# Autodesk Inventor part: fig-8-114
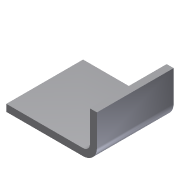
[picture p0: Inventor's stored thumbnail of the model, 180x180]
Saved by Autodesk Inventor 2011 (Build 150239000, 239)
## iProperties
Created: 2009-09
Part Number: fig-8-114
Document SubType Name: Modeling
Designer: Sham
Density: 1 g/cm^3
Author: Sham
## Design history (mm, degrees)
sketch "Sketch1"
  geometry: L1 (-33.976, 22)-(0, 22); L2 (0, 22)-(0, 0); L3 (0, 0)-(-33.976, 0); L4 (-33.976, 0)-(-33.976, 22)
  constraints: 8 end point, 2 parallel, 1 horizontal, 1 perpendicular
extrude "Extrusion1" new body sketch "Sketch1" distance "d0" = 2; taper "d1" = 0 deg
sketch "Sketch2"
  geometry: L1 (-12, 22)-(-12, 0)
  constraints: 2 end point
feature "Bend Part1" sketch "Sketch2" dims "d5" = 90 deg, "d6" = 2
body "Solid1"
